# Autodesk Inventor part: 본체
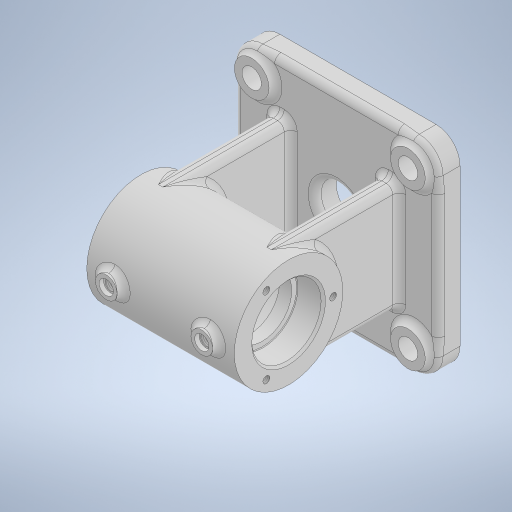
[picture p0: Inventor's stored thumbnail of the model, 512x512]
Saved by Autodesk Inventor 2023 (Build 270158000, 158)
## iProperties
Created: 2025-10
Part Number: 본체
Material: 일반
Document SubType Name: Modeling
Designer: home
Density: 1 g/cm^3
Appearance: 기본값
Author: home
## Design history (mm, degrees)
sketch "스케치1"
  geometry: L1 (47, -47)-(-47, -47); L2 (-47, -47)-(-47, 47); L3 (-47, 47)-(47, 47); L4 (47, 47)-(47, -47); L5 (47, -47)-(-47, 47); L6 (-47, -47)-(47, 47); 1 further point
  constraints: 12 end point, 2 midpoint, 2 parallel, 1 horizontal, 1 perpendicular
  dimensions: "d0" = 94 distance of L2.end L3.end; "d1" = 94 distance of L3.end L1.start
extrude "돌출1" new body sketch "스케치1" distance "d2" = 10; taper "d3" = 0 deg
fillet "모깎기1" dims "d4" = 11
sketch "스케치2"
  geometry: C1 r 8 at (-36, 36); C2 r 8 at (36, 36); C3 r 8 at (36, -36); C4 r 8 at (-36, -36); A1 r 11 centre (-36, 36) between (-36, 47) and (-47, 36) reference; A2 r 11 centre (-36, -36) between (-47, -36) and (-36, -47) reference; A3 r 11 centre (36, -36) between (36, -47) and (47, -36) reference; A4 r 11 centre (36, 36) between (47, 36) and (36, 47) reference; 1 further point
  constraints: 4 centre point, 4 coincident
  dimensions: "d5" = 16 diameter of C1; "d6" = 16 diameter of C2; "d7" = 16 diameter of C3; "d8" = 16 diameter of C4
extrude "돌출2" join sketch "스케치2" distance "d9" = 3; taper "d10" = 0 deg
fillet "모깎기2" dims "d11" = 3
sketch "스케치3"
  geometry: C1 r 8 at (0, 0) reference; C2 r 8 at (-72, 0) reference; C3 r 8 at (-72, -72) reference; C4 r 8 at (0, -72) reference; 5 further points
  constraints: 4 coincident
hole "구멍1" sketch "스케치3" at (-72, 0), (0, 0), (0, -72), (-72, -72) diameter "d12" = 9; stored, may be unused: countersink angle "d16" = 90 deg, drill point angle "d18" = 118 deg; dims "d13" = 12, "d14" = 4, "d15" = 2, "d17" = 8
sketch "스케치4"
  geometry: L1 (72.174, 66)-(-70.978, 66); L2 (34, 66)-(34, 91); L3 (-36, 10)-(36, 10) reference; L4 (0, 10)-(0, 115.236); L5 (34, 91)-(0, 91); L6 (34, 82)-(22, 82); L7 (22, 82)-(22, 79.5); L8 (22, 79.5)-(16.258, 79.5); L9 (47, 0)-(36, 0) reference; L10 (16.258, 79.5)-(5, 86); L11 (5, 86)-(0, 86); L12 (-34, 82)-(-22, 82); L13 (-22, 82)-(-22, 79.5); L14 (-16.258, 79.5)-(-5, 86); L15 (-5, 86)-(0, 86); L16 (-34, 91)-(0, 91); L17 (-22, 79.5)-(-16.258, 79.5); L18 (-34, 82)-(-34, 91); 1 further point
  constraints: 32 end point, 6 symmetric about line, 5 perpendicular, 4 point on line, 3 vertical, 1 horizontal, 1 midpoint
  dimensions: "d19" = 12 distance from line of L2 L7.end; "d20" = 66 distance between parallel lines of L9 L1; "d22" = 34 distance between parallel lines of L2 L4; "d23" = 32 diameter of L6 L1; "d25" = 40 diameter of L11 L1; "d26" = 5 distance from line of L4 L10.end; "d27" = 27 diameter of L8 L1; "d28" = 30 deg angle of L8 L10; "d29" = 50 diameter of L5 L1
revolve "회전1" sketch "스케치4" stored, may be unused: angle "d30" = 90 deg
sketch "스케치5"
  geometry: L1 (47, -36)-(47, 36) reference; L2 (-47, 36)-(-47, -36) reference; L3 (-36, -47)-(36, -47) reference; L4 (36, 47)-(-36, 47) reference; L5 (-29, 25)-(-21, 25); L6 (-21, 25)-(-21, -25); L7 (-21, -25)-(-29, -25); L8 (-29, -25)-(-29, 25); 2 further points
  constraints: 8 end point, 2 parallel, 1 horizontal, 1 midpoint, 1 perpendicular
  dimensions: "d32" = 50 distance of L7.end L5.start; "d33" = 8 distance of L5.start L5.end; "d34" = 21 distance from line of point (0, 0) L6; "d35" = 0 vertical distance of point (-21, 0) point (0, 0)
extrude "돌출3" join sketch "스케치5" stored distance "d36" = 3; taper "d37" = 0 deg
fillet "모깎기3" dims "d38" = 3
fillet "모깎기4" dims "d39" = 3
fillet "모깎기5" dims "d40" = 3
node "작업 평면2"
sketch "스케치6"
  geometry: L1 (-34, 25)-(-34, -25) reference; C1 r 5 at (-22, 0); 1 further point
  constraints: 1 centre point
  dimensions: "d42" = 10 diameter of C1; "d43" = 12 distance from line of L1 C1.centre
extrude "돌출4" join sketch "스케치6" stored distance "d44" = 10; taper "d45" = 0 deg
sketch "스케치7"
  geometry: C1 r 5 at (0, 0) reference; C2 r 5 at (-44, 0) reference; 3 further points
  constraints: 2 coincident
hole "구멍2" sketch "스케치7" at (0, 0), (-44, 0) diameter "d46" = 5.1881; stored, may be unused: countersink angle "d50" = 90 deg, drill point angle "d52" = 118 deg; dims "d47" = 12, "d48" = 6.6, "d49" = 2, "d51" = 16
sketch "스케치8" dims "d53" = 41
  geometry: L1 (0, 0)-(-20.5, 0); C1 r 16 at (0, 0) reference; 2 further points
  constraints: 2 coincident, 2 end point, 1 horizontal, 1 horizontal alignment, 2 other
hole "구멍3" sketch "스케치8" at (-20.5, 0) diameter "d54" = 3.242; stored, may be unused: countersink angle "d58" = 90 deg, drill point angle "d60" = 118 deg; dims "d55" = 8, "d56" = 6.6, "d57" = 2, "d59" = 10
fillet "모깎기6" dims "d64" = 3
node "작업 평면4"
sketch "스케치9"
  geometry: C1 r 6 at (0, 0); 1 further point
  constraints: 1 centre point, 1 coincident
  dimensions: "d67" = 12 diameter of C1
extrude "돌출5" join sketch "스케치9" stored distance "d68" = 10; taper "d69" = 0 deg
sketch "스케치10"
  geometry: 2 further points
  constraints: 1 coincident
hole "구멍4" sketch "스케치10" at (0, 0) diameter "d70" = 5.1881; stored, may be unused: countersink angle "d74" = 90 deg, drill point angle "d76" = 0 deg; dims "d71" = 12, "d72" = 4, "d73" = 2, "d75" = 16
chamfer "모따기1" distance "d77" = 1; stored, may be unused: second distance "d78" = 2, angle "d79" = 45 deg
chamfer "모따기2" distance "d80" = 0.3; stored, may be unused: second distance "d81" = 2, angle "d82" = 45 deg
sketch "스케치11"
  geometry: 2 further points
  constraints: 1 coincident
hole "구멍5" sketch "스케치11" at (0, 0) diameter "d83" = 20; stored, may be unused: countersink angle "d87" = 90 deg, drill point angle "d89" = 0 deg; dims "d84" = 12, "d85" = 4, "d86" = 2, "d88" = 15
fillet "모깎기7" dims "d90" = 3
node "작업 평면5"
sketch "스케치12"
  geometry: L1 (-15.558, 3.5)-(15.558, 3.5); L2 (15.558, 3.5)-(15.558, -3.5); L3 (15.558, -3.5)-(-15.558, -3.5); L4 (-15.558, -3.5)-(-15.558, 3.5); L5 (-36, -66)-(36, -66) reference; 5 further points
  constraints: 3 midpoint, 2 other
  dimensions: "d91" = 0 vertical distance of point (26, 0) point (15.558, 0); "d92" = 0 horizontal distance of point (0, -66) point (0, 3.5)
feature "엠보싱1" sketch "스케치12" dims "d0" = 94, "d1" = 94, "d93" = 0.5, "d94" = 0
fillet "모깎기8" dims "d95" = 3
node "솔리드1"
mirror "미러1"
mirror "미러2"
pattern_circular "원형 패턴1" dims angle "d62" = 360 deg
mirror "미러3"
feature "A9D066F2-1C7D-4E18-AEED-F7BC21143FA4" dims "d12" = 9, "d13" = 12, "d14" = 4, "d15" = 2, "d16" = 90 deg, "d17" = 8, "d18" = 118 deg
other parameters: "d41" = -94, "d66" = -56
